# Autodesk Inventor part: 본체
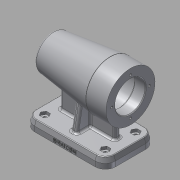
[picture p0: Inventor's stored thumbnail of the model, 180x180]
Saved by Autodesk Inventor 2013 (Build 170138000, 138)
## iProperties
Created: 2017-01
Part Number: 본체
Material: 알루미늄 6061
Document SubType Name: Modeling
Designer: Administrator
Density: 2.71 g/cm^3
Mass: 793.917 g
Surface Area: 667.319 cm^2
Volume: 292.958 cm^3
Author: Administrator
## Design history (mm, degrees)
sketch "스케치1"
  geometry: L1 (-56, -35)-(56, -35); L2 (56, -35)-(56, 35); L3 (56, 35)-(-56, 35); L4 (-56, 35)-(-56, -35); L5 (-56, -35)-(56, 35); L6 (56, -35)-(-56, 35); 1 further point
  constraints: 12 end point, 2 midpoint, 2 parallel, 1 horizontal, 1 perpendicular
  dimensions: "d0" = 70 distance of L3.end L1.start; "d2" = 112 distance of L2.end L3.end
extrude "돌출1" new body sketch "스케치1" distance "d3" = 14; taper "d4" = 0 deg
sketch "스케치2"
  geometry: L1 (56, 74)-(-56, 74); L2 (-56, 0)-(56, 0) reference; L3 (-56, 95)-(-41, 95); L4 (-41, 95)-(-41, 98); L5 (-41, 98)-(13, 98); L6 (13, 98)-(13, 95); L7 (13, 95)-(25, 95); L8 (25, 95)-(25, 91.5); L9 (25, 91.5)-(43, 91.5); L10 (43, 91.5)-(43, 90); L11 (43, 90)-(47, 90); L12 (47, 90)-(47, 84.5); L13 (52.27, 98.144)-(-28, 108); L14 (-28, 108)-(-56, 108); L15 (-56, 95)-(-56, 108); L16 (47, 84.5)-(50, 84.5); L17 (50, 84.5)-(50, 74); L18 (56, 74)-(50, 74); A1 r 80 centre (-24, 74) between (56, 74) and (52.27, 98.144); 1 further point
  constraints: 34 end point, 6 parallel, 6 perpendicular, 3 vertical alignment, 2 collinear, 2 point on circle, 2 point on line, 1 centre point, 1 horizontal
  dimensions: "d5" = 74 distance between parallel lines of L2 L1; "d7" = 42 diameter of L3 L1; "d8" = 48 diameter of L5 L1; "d9" = 42 diameter of L7 L1; "d10" = 35 diameter of L9 L1; "d11" = 32 diameter of L11 L1; "d13" = 15 distance of L3.start L3.end; "d14" = 54 distance of L4.end L5.end; "d15" = 12 distance of L6.end L7.end; "d16" = 18 distance of L8.end L9.end; "d18" = 4 distance of L10.end L11.end; "d21" = 3 distance of L12.end L16.end; "d22" = 21 diameter of L16 L1; "d23" = 28 distance of L13.end L14.end; "d24" = 80 radius of A1; "d25" = 7 deg angle of L14 L13; "d26" = 68 diameter of L14 L1
revolve "회전1" sketch "스케치2" stored, may be unused: angle "d27" = 90 deg
sketch "스케치3"
  geometry: L1 (-56, 35)-(-56, -35) reference; L2 (38, -4)-(-38, -4); L3 (-38, -4)-(-38, 4); L4 (-38, 4)-(38, 4); L5 (38, 4)-(38, -4); L6 (38, -4)-(-38, 4); L7 (-38, -4)-(38, 4); 1 further point
  constraints: 12 end point, 2 midpoint, 2 parallel, 1 horizontal, 1 perpendicular
  dimensions: "d30" = 8 distance of L4.end L2.start; "d32" = 18 distance between parallel lines of L1 L3
extrude "돌출2" join sketch "스케치3" stored distance "d33" = 10; taper "d34" = 0 deg
sketch "스케치4" dims "d37" = 52
  geometry: L1 (0, 0)-(-26, 0); C1 r 21 at (0, 0) reference; 2 further points
  constraints: 2 coincident, 2 end point, 1 horizontal, 1 horizontal alignment, 2 other
hole "구멍1" sketch "스케치4" at (-26, 0) diameter "d39" = 3.242; stored, may be unused: countersink angle "d43" = 90 deg, drill point angle "d45" = 118 deg; dims "d40" = 8, "d41" = 4, "d42" = 2, "d44" = 11
fillet "모깎기1" dims "d49" = 14
sketch "스케치5" dims "d50" = 10
  geometry: L1 (-39.113, 26)-(-36.226, 21); L2 (-36.226, 21)-(-39.113, 16); L3 (-39.113, 16)-(-44.887, 16); L4 (-44.887, 16)-(-47.774, 21); L5 (-47.774, 21)-(-44.887, 26); L6 (-44.887, 26)-(-39.113, 26); A1 r 14 centre (-42, 21) between (-42, 35) and (-56, 21) reference; 4 further points
  constraints: 12 end point, 2 coincident, 1 midpoint, 1 vertical alignment, 15 other
  dimensions: "d52" = 10 vertical distance of L1.start L3.end
extrude "돌출3" cut sketch "스케치5" distance "d53" = 4; taper "d54" = 0 deg
sketch "스케치6"
  geometry: L1 (-39.113, 16)-(-44.887, 16) reference; L2 (-47.774, 21)-(-36.226, 21); C1 r 2.5 at (-42, 21); 1 further point
  constraints: 2 end point, 1 centre point, 1 midpoint, 1 parallel
  dimensions: "d55" = 5 diameter of C1
extrude "돌출4" cut sketch "스케치6" stored distance "d57" = 4; taper "d58" = 0 deg
fillet "모깎기2" dims "d65" = 0.3
fillet "모깎기3" dims "d66" = 3
fillet "모깎기4" dims "d67" = 3
sketch "스케치7"
  geometry: L1 (4, 40.259)-(4, 48.415) reference; L2 (-4, 48.415)-(-4, 40.259) reference; L3 (21, 14)-(26, 14) reference; L4 (16, 14)-(21, 14) reference; L5 (-21, 14)-(21, 14) reference; L6 (23, 14)-(15.708, 55.352); L7 (35, 0)-(35, 14) reference; L8 (21, 14)-(35, 14) reference; C1 r 24 at (0, 74) reference; C2 r 24 at (0, 74) reference; C3 r 24 at (0, 74) reference; A1 r 33.978 centre (0, 74) between (4, 40.259) and (-4, 40.259) reference; A2 r 25.896 centre (0, 74) between (-4, 48.415) and (4, 48.415) reference; 2 further points
  constraints: 2 end point, 1 point on line, 2 other
  dimensions: "d68" = 12 distance from line of L6.start L7; "d69" = 100 deg angle of L8 L6
feature "리브1" sketch "스케치7" dims "d70" = 8, "d71" = 8, "d72" = 0, "d73" = 0, "d74" = 1, "d75" = 1
fillet "모깎기5" dims "d76" = 3
fillet "모깎기6" dims "d77" = 3
sketch "스케치8"
  geometry: L1 (24.2, 6.402)-(59.8, 6.402); L2 (59.8, 6.402)-(59.8, 1.598); L3 (59.8, 1.598)-(24.2, 1.598); L4 (24.2, 1.598)-(24.2, 6.402); L5 (42, 6.402)-(42, 1.598); L6 (24.2, 4)-(59.8, 4); L7 (98, 0)-(84, 0) reference; L8 (-14, 14)-(-14, 0) reference; 1 further point
  constraints: 4 end point, 4 midpoint, 2 other
  dimensions: "d81" = 4 distance from line of L7 L6.end; "d82" = 56 distance between parallel lines of L8 L5; "d83" = 35.59979 distance of L6.start L6.end; "d84" = 4.80326 distance of L5.start L5.end
extrude "돌출5" join sketch "스케치8" distance "d85" = 0.5; taper "d86" = 0 deg
chamfer "모따기1" distance "d87" = 7; stored, may be unused: second distance "d88" = 2, angle "d89" = 15 deg
fillet "모깎기7" dims "d90" = 1
chamfer "모따기2" distance "d91" = 1; stored, may be unused: second distance "d92" = 2, angle "d93" = 15 deg
fillet "모깎기8" dims "d94" = 3
node "솔리드1"
pattern_circular "원형 패턴1" dims angle "d47" = 360 deg
pattern_linear "직사각형 패턴1" dims "d61" = 42, "d64" = 84
mirror "대칭1"
node "투영된 루프1"
node "투영된 루프2"
